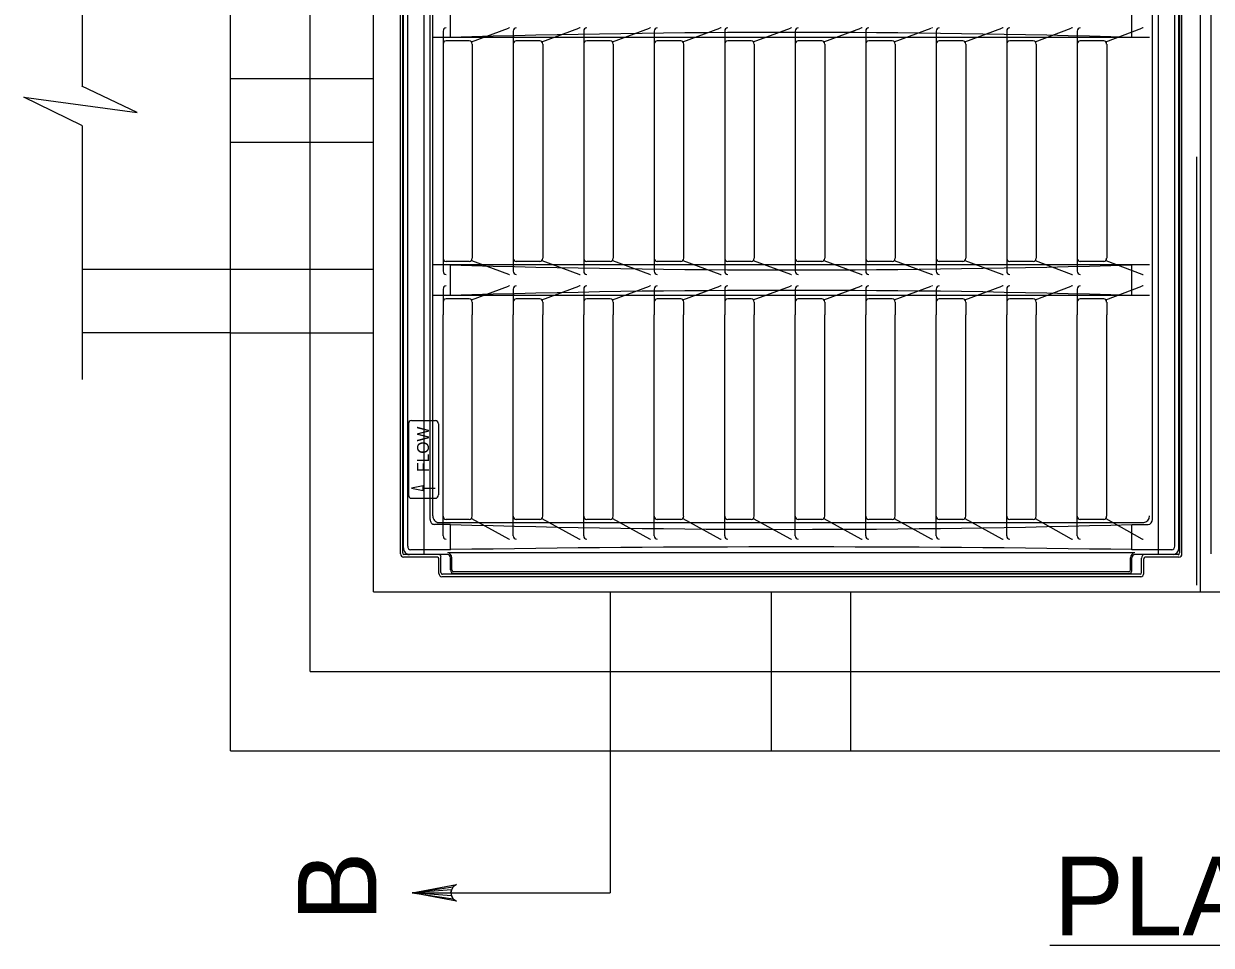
# Model space of a CAD drawing. Extents: x 6.91 to 13.84, y 0.35 to 9.99.
# Drawn here: x 7.133 to 8.644, y 7.952 to 9.125 of the extents above; entities that cross this region are included whole.
import ezdxf

# ---------------------------------------------------------------- set-up
doc = ezdxf.new("R2010")
doc.units = 0
for name, color, linetype in [('DETL-DIMS', 7, 'Continuous'), ('DETL-LINE', 7, 'Continuous'), ('DETL-NOTE', 7, 'Continuous'), ('DETL-TITL', 7, 'Continuous')]:
    doc.layers.add(name, color=color, linetype=linetype)

msp = doc.modelspace()

# ---------------------------------------------------------------- linework, layer by layer
at = {"layer": 'DETL-DIMS'}
for p in [(7.8795, 8.4019), (7.6276, 8.0189)]:
    msp.add_line(p, (7.8795, 8.0189), dxfattribs=at)
msp.add_lwpolyline([(7.6276, 8.0189), (7.6841, 8.0295), (7.6798, 8.0265), (7.6775, 8.0227), (7.6769, 8.0189), (7.6775, 8.0151), (7.6798, 8.0113), (7.6841, 8.0083), (7.6276, 8.0189), (7.6798, 8.0113), (7.6775, 8.0151), (7.6276, 8.0189), (7.6769, 8.0189), (7.6775, 8.0227), (7.6276, 8.0189), (7.6798, 8.0265)], dxfattribs=at)
at = {"layer": 'DETL-LINE'}
for p, q in [((7.3965, 8.1996), (7.3965, 9.7427)), ((7.4976, 8.3007), (7.4976, 9.6214)), ((7.5785, 8.4019), (7.5785, 9.5203)), ((8.6303, 9.5203), (8.6303, 8.4019)), ((7.6128, 8.4504), (7.6128, 9.4776)), ((7.6156, 8.4514), (7.6156, 9.4765)), ((7.6427, 8.4495), (7.6427, 9.476)), ((8.577, 8.4495), (8.577, 9.476)), ((8.6041, 8.4514), (8.6041, 9.4765)), ((8.6069, 8.4504), (8.6069, 9.4776)), ((8.6443, 8.4504), (8.6443, 9.4776)), ((7.6219, 8.4599), (7.6219, 9.4656)), ((8.5979, 8.4599), (8.5979, 9.4656)), ((8.5694, 8.4942), (8.5694, 9.4313)), ((7.6503, 8.4942), (7.6503, 9.4278)), ((7.6539, 8.4988), (7.6539, 9.4267)), ((7.2076, 9.3519), (7.2076, 9.0456)), ((7.6764, 9.1074), (7.6764, 9.1463)), ((8.5434, 9.1074), (8.5434, 9.1463)), ((8.5658, 9.1074), (7.6539, 9.1074)), ((7.3965, 9.0551), (7.5785, 9.0551)), ((7.2076, 8.9955), (7.2076, 8.6723)), ((7.3965, 8.9742), (7.5785, 8.9742)), ((8.626, 8.4104), (8.626, 8.9554)), ((7.2076, 8.8124), (7.5785, 8.8124)), ((8.5658, 8.8181), (7.6539, 8.8181)), ((7.6764, 8.7791), (7.6764, 8.8181)), ((8.5434, 8.7791), (8.5434, 8.8181)), ((8.5658, 8.7791), (7.6539, 8.7791)), ((7.3965, 8.7315), (7.2076, 8.7315)), ((7.3965, 8.7315), (7.5785, 8.7315)), ((7.6764, 8.4877), (7.6559, 8.4877)), ((7.6614, 8.4902), (8.5583, 8.4902)), ((7.6764, 8.4556), (7.6764, 8.4877)), ((8.5434, 8.4877), (8.5638, 8.4877)), ((8.5434, 8.4556), (8.5434, 8.4877)), ((7.6596, 8.4461), (7.6166, 8.4461)), ((7.6624, 8.4493), (7.6175, 8.4493)), ((7.6764, 8.4556), (7.6256, 8.4556)), ((7.6427, 8.4493), (7.6427, 8.4495)), ((7.6642, 8.4266), (7.6642, 8.4471)), ((8.5471, 8.4516), (7.6733, 8.4516)), ((8.5941, 8.4556), (8.5434, 8.4556)), ((8.6022, 8.4493), (8.5593, 8.4493)), ((8.6032, 8.4461), (8.5602, 8.4461)), ((8.577, 8.4493), (8.577, 8.4495)), ((7.6614, 8.4255), (7.6614, 8.4439)), ((7.6781, 8.4298), (7.6781, 8.4452)), ((8.5416, 8.4298), (8.5416, 8.4452)), ((8.5555, 8.4266), (8.5555, 8.445)), ((8.5583, 8.4255), (8.5583, 8.4439)), ((8.5546, 8.4212), (7.6652, 8.4212)), ((8.5537, 8.4245), (7.6661, 8.4245)), ((8.5396, 8.4276), (7.6801, 8.4276)), ((7.5785, 8.4019), (9.682, 8.4019)), ((8.0842, 8.4019), (8.0842, 8.1996)), ((8.1853, 8.4019), (8.1853, 8.1996)), ((7.4976, 8.3007), (9.7629, 8.3007)), ((7.3965, 8.1996), (9.864, 8.1996))]:
    msp.add_line(p, q, dxfattribs=at)
msp.add_lwpolyline([(7.2071, 8.9955), (7.1334, 9.0316), (7.2777, 9.012), (7.2071, 9.0456)], dxfattribs=at)
for centre, major_axis, start_param, end_param in [((8.1099, -10.1659), (0, 19.2797), 6.257325, 6.309046), ((8.1099, 28.0913), (0, 19.2797), 3.115732, 3.167453), ((8.1099, -10.4941), (0, 19.2797), 6.257325, 6.309046), ((7.6559, 8.4942), (0, 0.00645), 1.570796, 3.141593), ((7.6614, 8.4988), (0, 0.0086), 1.570796, 3.141593), ((8.5583, 8.4988), (0, 0.0086), 3.141593, 4.712389), ((8.5638, 8.4942), (0, 0.00645), 3.141593, 4.712389), ((8.1099, 28.6478), (0, 20.1663), 3.116869, 3.166316), ((7.6166, 8.4504), (0, 0.0043), 1.570796, 3.141593), ((7.6175, 8.4514), (0, 0.00215), 1.570796, 3.141593), ((7.6256, 8.4599), (0, 0.0043), 1.570796, 3.141593), ((7.6596, 8.4439), (0, 0.00215), 4.712389, 6.283185), ((7.6624, 8.4471), (0, 0.00215), 4.712389, 6.283185), ((7.6726, 8.4452), (0, 0.00632), 4.712389, 6.283185), ((8.1099, -27.686), (0, 36.1451), 6.269392, 6.296978), ((8.5471, 8.4452), (0, 0.00632), 0, 1.570796), ((8.5593, 8.445), (0, 0.0043), 0, 1.570796), ((8.5602, 8.4439), (0, 0.00215), 0, 1.570796), ((8.5941, 8.4599), (0, 0.0043), 3.141593, 4.712389), ((8.6022, 8.4514), (0, 0.00215), 3.141593, 4.712389), ((8.6032, 8.4504), (0, 0.0043), 3.141593, 4.712389), ((7.6652, 8.4255), (0, 0.0043), 1.570796, 3.141593), ((7.6661, 8.4266), (0, 0.00215), 1.570796, 3.141593), ((7.6801, 8.4298), (0, 0.00227), 1.570796, 3.141593), ((8.5396, 8.4298), (0, 0.00227), 3.141593, 4.712389), ((8.5537, 8.4266), (0, 0.00215), 3.141593, 4.712389), ((8.5546, 8.4255), (0, 0.0043), 3.141593, 4.712389)]:
    msp.add_ellipse(centre, major_axis=major_axis, ratio=0.869565, start_param=start_param, end_param=end_param, dxfattribs=at)
at = {"layer": 'DETL-NOTE'}
for p, q in [((7.6166, 8.4581), (7.6166, 9.4674)), ((8.6032, 8.4581), (8.6032, 9.4674)), ((7.667, 9.1153), (7.667, 8.8101)), ((7.7029, 9.1018), (7.75, 9.1192)), ((7.7562, 9.1153), (7.7562, 8.8101)), ((7.7926, 9.1018), (7.8397, 9.1192)), ((7.8459, 9.1153), (7.8459, 8.8101)), ((7.8823, 9.1018), (7.9294, 9.1192)), ((7.9356, 9.1153), (7.9356, 8.8101)), ((7.9719, 9.1018), (8.0191, 9.1192)), ((8.0253, 9.1153), (8.0253, 8.8101)), ((8.0616, 9.1018), (8.1088, 9.1192)), ((8.115, 9.1153), (8.115, 8.8101)), ((8.1513, 9.1018), (8.1985, 9.1192)), ((8.2047, 9.1153), (8.2047, 8.8101)), ((8.241, 9.1018), (8.2881, 9.1192)), ((8.2944, 9.1153), (8.2944, 8.8101)), ((8.3307, 9.1018), (8.3778, 9.1192)), ((8.3841, 9.1153), (8.3841, 8.8101)), ((8.4204, 9.1018), (8.4661, 9.1192)), ((8.4737, 9.1153), (8.4737, 8.8101)), ((8.5101, 9.1018), (8.5558, 9.1192)), ((7.7002, 9.1031), (7.6707, 9.1031)), ((7.704, 9.0988), (7.704, 8.8267)), ((7.7899, 9.1031), (7.76, 9.1031)), ((7.7937, 9.0988), (7.7937, 8.8267)), ((7.8796, 9.1031), (7.8496, 9.1031)), ((7.8834, 9.0988), (7.8834, 8.8267)), ((7.9693, 9.1031), (7.9393, 9.1031)), ((7.973, 9.0988), (7.973, 8.8267)), ((8.059, 9.1031), (8.029, 9.1031)), ((8.0627, 9.0988), (8.0627, 8.8267)), ((8.1487, 9.1031), (8.1187, 9.1031)), ((8.1524, 9.0988), (8.1524, 8.8267)), ((8.2384, 9.1031), (8.2084, 9.1031)), ((8.2421, 9.0988), (8.2421, 8.8267)), ((8.3281, 9.1031), (8.2981, 9.1031)), ((8.3318, 9.0988), (8.3318, 8.8267)), ((8.4178, 9.1031), (8.3878, 9.1031)), ((8.4215, 9.0988), (8.4215, 8.8267)), ((8.5074, 9.1031), (8.4775, 9.1031)), ((8.5112, 9.0988), (8.5112, 8.8267)), ((7.7029, 8.8237), (7.75, 8.8063)), ((7.7926, 8.8237), (7.8397, 8.8063)), ((7.8823, 8.8237), (7.9294, 8.8063)), ((7.9719, 8.8237), (8.0191, 8.8063)), ((8.0616, 8.8237), (8.1088, 8.8063)), ((8.1513, 8.8237), (8.1985, 8.8063)), ((8.241, 8.8237), (8.2881, 8.8063)), ((8.3307, 8.8237), (8.3778, 8.8063)), ((8.4204, 8.8237), (8.4661, 8.8063)), ((8.5101, 8.8237), (8.5558, 8.8063)), ((7.7002, 8.8224), (7.6707, 8.8224)), ((7.7899, 8.8224), (7.76, 8.8224)), ((7.8796, 8.8224), (7.8496, 8.8224)), ((7.9693, 8.8224), (7.9393, 8.8224)), ((8.059, 8.8224), (8.029, 8.8224)), ((8.1487, 8.8224), (8.1187, 8.8224)), ((8.2384, 8.8224), (8.2084, 8.8224)), ((8.3281, 8.8224), (8.2981, 8.8224)), ((8.4178, 8.8224), (8.3878, 8.8224)), ((8.5074, 8.8224), (8.4775, 8.8224)), ((7.667, 8.7871), (7.667, 8.7546)), ((7.7029, 8.7736), (7.75, 8.791)), ((7.7562, 8.7871), (7.7562, 8.7546)), ((7.7926, 8.7736), (7.8397, 8.791)), ((7.8459, 8.7871), (7.8459, 8.7546)), ((7.8823, 8.7736), (7.9294, 8.791)), ((7.9356, 8.7871), (7.9356, 8.7546)), ((7.9719, 8.7736), (8.0191, 8.791)), ((8.0253, 8.7871), (8.0253, 8.7546)), ((8.0616, 8.7736), (8.1088, 8.791)), ((8.115, 8.7871), (8.115, 8.7546)), ((8.1513, 8.7736), (8.1985, 8.791)), ((8.2047, 8.7871), (8.2047, 8.7546)), ((8.241, 8.7736), (8.2881, 8.791)), ((8.2944, 8.7871), (8.2944, 8.7546)), ((8.3307, 8.7736), (8.3778, 8.791)), ((8.3841, 8.7871), (8.3841, 8.7546)), ((8.4204, 8.7736), (8.4661, 8.791)), ((8.4737, 8.7871), (8.4737, 8.7546)), ((8.5101, 8.7736), (8.5558, 8.791)), ((7.7002, 8.7748), (7.6707, 8.7748)), ((7.704, 8.7705), (7.704, 8.7546)), ((7.7899, 8.7748), (7.76, 8.7748)), ((7.7937, 8.7705), (7.7937, 8.7546)), ((7.8796, 8.7748), (7.8496, 8.7748)), ((7.8834, 8.7705), (7.8834, 8.7546)), ((7.9693, 8.7748), (7.9393, 8.7748)), ((7.973, 8.7705), (7.973, 8.7546)), ((8.059, 8.7748), (8.029, 8.7748)), ((8.0627, 8.7705), (8.0627, 8.7546)), ((8.1487, 8.7748), (8.1187, 8.7748)), ((8.1524, 8.7705), (8.1524, 8.7546)), ((8.2384, 8.7748), (8.2084, 8.7748)), ((8.2421, 8.7705), (8.2421, 8.7546)), ((8.3281, 8.7748), (8.2981, 8.7748)), ((8.3318, 8.7705), (8.3318, 8.7546)), ((8.4178, 8.7748), (8.3878, 8.7748)), ((8.4215, 8.7705), (8.4215, 8.7546)), ((8.5074, 8.7748), (8.4775, 8.7748)), ((8.5112, 8.7705), (8.5112, 8.7546)), ((7.667, 8.4732), (7.667, 8.7546)), ((7.704, 8.4983), (7.704, 8.7546)), ((7.7562, 8.4732), (7.7562, 8.7546)), ((7.7937, 8.4983), (7.7937, 8.7546)), ((7.8459, 8.4732), (7.8459, 8.7546)), ((7.8834, 8.4983), (7.8834, 8.7546)), ((7.9356, 8.4732), (7.9356, 8.7546)), ((7.973, 8.4983), (7.973, 8.7546)), ((8.0253, 8.4732), (8.0253, 8.7546)), ((8.0627, 8.4983), (8.0627, 8.7546)), ((8.115, 8.4732), (8.115, 8.7546)), ((8.1524, 8.4983), (8.1524, 8.7546)), ((8.2047, 8.4732), (8.2047, 8.7546)), ((8.2421, 8.4983), (8.2421, 8.7546)), ((8.2944, 8.4732), (8.2944, 8.7546)), ((8.3318, 8.4983), (8.3318, 8.7546)), ((8.3841, 8.4732), (8.3841, 8.7546)), ((8.4215, 8.4983), (8.4215, 8.7546)), ((8.4737, 8.4732), (8.4737, 8.7546)), ((8.5112, 8.4983), (8.5112, 8.7546)), ((7.6229, 8.6156), (7.6229, 8.5253)), ((7.6266, 8.6199), (7.6572, 8.6199)), ((7.661, 8.6156), (7.661, 8.5253)), ((7.6416, 8.5339), (7.657, 8.5339)), ((7.6266, 8.521), (7.6572, 8.521)), ((7.7002, 8.4941), (7.6707, 8.4941)), ((7.7029, 8.4953), (7.75, 8.4693)), ((7.7899, 8.4941), (7.76, 8.4941)), ((7.7926, 8.4953), (7.8397, 8.4693)), ((7.8796, 8.4941), (7.8496, 8.4941)), ((7.8823, 8.4953), (7.9294, 8.4693)), ((7.9693, 8.4941), (7.9393, 8.4941)), ((7.9719, 8.4953), (8.0191, 8.4693)), ((8.059, 8.4941), (8.029, 8.4941)), ((8.0616, 8.4953), (8.1088, 8.4693)), ((8.1487, 8.4941), (8.1187, 8.4941)), ((8.1513, 8.4953), (8.1985, 8.4693)), ((8.2384, 8.4941), (8.2084, 8.4941)), ((8.241, 8.4953), (8.2881, 8.4693)), ((8.3281, 8.4941), (8.2981, 8.4941)), ((8.3307, 8.4953), (8.3778, 8.4693)), ((8.4178, 8.4941), (8.3878, 8.4941)), ((8.4204, 8.4953), (8.4661, 8.4693)), ((8.5074, 8.4941), (8.4775, 8.4941)), ((8.5101, 8.4953), (8.5558, 8.4693)), ((7.6726, 8.4495), (7.624, 8.4495)), ((8.5957, 8.4495), (8.5471, 8.4495)), ((7.6764, 8.4298), (7.6764, 8.4452)), ((7.6764, 8.4409), (7.6764, 8.4451)), ((8.5434, 8.4298), (8.5434, 8.4452)), ((7.6801, 8.4255), (8.5396, 8.4255))]:
    msp.add_line(p, q, dxfattribs=at)
msp.add_lwpolyline([(7.6416, 8.531), (7.6416, 8.5367), (7.6266, 8.5339)], close=True, dxfattribs=at)
for centre, major_axis, start_param, end_param in [((7.6707, 9.1153), (0, 0.0043), 0, 1.570796), ((7.7516, 9.1153), (0, 0.0043), 0, 0.447297), ((7.76, 9.1153), (0, 0.0043), 0, 1.570796), ((7.8413, 9.1153), (0, 0.0043), 0, 0.447297), ((7.8496, 9.1153), (0, 0.0043), 0, 1.570796), ((7.931, 9.1153), (0, 0.0043), 0, 0.447297), ((7.9393, 9.1153), (0, 0.0043), 0, 1.570796), ((8.0207, 9.1153), (0, 0.0043), 0, 0.447297), ((8.029, 9.1153), (0, 0.0043), 0, 1.570796), ((8.1104, 9.1153), (0, 0.0043), 0, 0.447297), ((8.1187, 9.1153), (0, 0.0043), 0, 1.570796), ((8.2001, 9.1153), (0, 0.0043), 0, 0.447297), ((8.2084, 9.1153), (0, 0.0043), 0, 1.570796), ((8.2898, 9.1153), (0, 0.0043), 0, 0.447297), ((8.2981, 9.1153), (0, 0.0043), 0, 1.570796), ((8.3795, 9.1153), (0, 0.0043), 0, 0.447297), ((8.3878, 9.1153), (0, 0.0043), 0, 1.570796), ((8.4678, 9.1153), (0, 0.0043), 0, 0.447297), ((8.4775, 9.1153), (0, 0.0043), 0, 1.570796), ((8.5575, 9.1153), (0, 0.0043), 0, 0.447297), ((7.6707, 9.0988), (0, 0.0043), 0, 1.570796), ((7.7002, 9.0988), (0, 0.0043), 4.712389, 6.283185), ((7.76, 9.0988), (0, 0.0043), 0, 1.570796), ((7.7899, 9.0988), (0, 0.0043), 4.712389, 6.283185), ((7.8496, 9.0988), (0, 0.0043), 0, 1.570796), ((7.8796, 9.0988), (0, 0.0043), 4.712389, 6.283185), ((7.9393, 9.0988), (0, 0.0043), 0, 1.570796), ((7.9693, 9.0988), (0, 0.0043), 4.712389, 6.283185), ((8.029, 9.0988), (0, 0.0043), 0, 1.570796), ((8.059, 9.0988), (0, 0.0043), 4.712389, 6.283185), ((8.1187, 9.0988), (0, 0.0043), 0, 1.570796), ((8.1487, 9.0988), (0, 0.0043), 4.712389, 6.283185), ((8.2084, 9.0988), (0, 0.0043), 0, 1.570796), ((8.2384, 9.0988), (0, 0.0043), 4.712389, 6.283185), ((8.2981, 9.0988), (0, 0.0043), 0, 1.570796), ((8.3281, 9.0988), (0, 0.0043), 4.712389, 6.283185), ((8.3878, 9.0988), (0, 0.0043), 0, 1.570796), ((8.4178, 9.0988), (0, 0.0043), 4.712389, 6.283185), ((8.4775, 9.0988), (0, 0.0043), 0, 1.570796), ((8.5074, 9.0988), (0, 0.0043), 4.712389, 6.283185), ((7.6707, 8.8267), (0, 0.0043), 1.570796, 3.141593), ((7.7002, 8.8267), (0, 0.0043), 3.141593, 4.712389), ((7.76, 8.8267), (0, 0.0043), 1.570796, 3.141593), ((7.7899, 8.8267), (0, 0.0043), 3.141593, 4.712389), ((7.8496, 8.8267), (0, 0.0043), 1.570796, 3.141593), ((7.8796, 8.8267), (0, 0.0043), 3.141593, 4.712389), ((7.9393, 8.8267), (0, 0.0043), 1.570796, 3.141593), ((7.9693, 8.8267), (0, 0.0043), 3.141593, 4.712389), ((8.029, 8.8267), (0, 0.0043), 1.570796, 3.141593), ((8.059, 8.8267), (0, 0.0043), 3.141593, 4.712389), ((8.1187, 8.8267), (0, 0.0043), 1.570796, 3.141593), ((8.1487, 8.8267), (0, 0.0043), 3.141593, 4.712389), ((8.2084, 8.8267), (0, 0.0043), 1.570796, 3.141593), ((8.2384, 8.8267), (0, 0.0043), 3.141593, 4.712389), ((8.2981, 8.8267), (0, 0.0043), 1.570796, 3.141593), ((8.3281, 8.8267), (0, 0.0043), 3.141593, 4.712389), ((8.3878, 8.8267), (0, 0.0043), 1.570796, 3.141593), ((8.4178, 8.8267), (0, 0.0043), 3.141593, 4.712389), ((8.4775, 8.8267), (0, 0.0043), 1.570796, 3.141593), ((8.5074, 8.8267), (0, 0.0043), 3.141593, 4.712389), ((7.6707, 8.8101), (0, 0.0043), 1.570796, 3.141593), ((7.76, 8.8101), (0, 0.0043), 1.570796, 3.141593), ((7.8496, 8.8101), (0, 0.0043), 1.570796, 3.141593), ((7.9393, 8.8101), (0, 0.0043), 1.570796, 3.141593), ((8.029, 8.8101), (0, 0.0043), 1.570796, 3.141593), ((8.1187, 8.8101), (0, 0.0043), 1.570796, 3.141593), ((8.2084, 8.8101), (0, 0.0043), 1.570796, 3.141593), ((8.2981, 8.8101), (0, 0.0043), 1.570796, 3.141593), ((8.3878, 8.8101), (0, 0.0043), 1.570796, 3.141593), ((8.4775, 8.8101), (0, 0.0043), 1.570796, 3.141593), ((7.7516, 8.8101), (0, 0.0043), 2.694296, 3.141593), ((7.8413, 8.8101), (0, 0.0043), 2.694296, 3.141593), ((7.931, 8.8101), (0, 0.0043), 2.694296, 3.141593), ((8.0207, 8.8101), (0, 0.0043), 2.694296, 3.141593), ((8.1104, 8.8101), (0, 0.0043), 2.694296, 3.141593), ((8.2001, 8.8101), (0, 0.0043), 2.694296, 3.141593), ((8.2898, 8.8101), (0, 0.0043), 2.694296, 3.141593), ((8.3795, 8.8101), (0, 0.0043), 2.694296, 3.141593), ((8.4678, 8.8101), (0, 0.0043), 2.694296, 3.141593), ((8.5575, 8.8101), (0, 0.0043), 2.694296, 3.141593), ((7.6707, 8.7871), (0, 0.0043), 0, 1.570796), ((7.7516, 8.7871), (0, 0.0043), 0, 0.447297), ((7.76, 8.7871), (0, 0.0043), 0, 1.570796), ((7.8413, 8.7871), (0, 0.0043), 0, 0.447297), ((7.8496, 8.7871), (0, 0.0043), 0, 1.570796), ((7.931, 8.7871), (0, 0.0043), 0, 0.447297), ((7.9393, 8.7871), (0, 0.0043), 0, 1.570796), ((8.0207, 8.7871), (0, 0.0043), 0, 0.447297), ((8.029, 8.7871), (0, 0.0043), 0, 1.570796), ((8.1104, 8.7871), (0, 0.0043), 0, 0.447297), ((8.1187, 8.7871), (0, 0.0043), 0, 1.570796), ((8.2001, 8.7871), (0, 0.0043), 0, 0.447297), ((8.2084, 8.7871), (0, 0.0043), 0, 1.570796), ((8.2898, 8.7871), (0, 0.0043), 0, 0.447297), ((8.2981, 8.7871), (0, 0.0043), 0, 1.570796), ((8.3795, 8.7871), (0, 0.0043), 0, 0.447297), ((8.3878, 8.7871), (0, 0.0043), 0, 1.570796), ((8.4678, 8.7871), (0, 0.0043), 0, 0.447297), ((8.4775, 8.7871), (0, 0.0043), 0, 1.570796), ((8.5575, 8.7871), (0, 0.0043), 0, 0.447297), ((7.6707, 8.7705), (0, 0.0043), 0, 1.570796), ((7.7002, 8.7705), (0, 0.0043), 4.712389, 6.283185), ((7.76, 8.7705), (0, 0.0043), 0, 1.570796), ((7.7899, 8.7705), (0, 0.0043), 4.712389, 6.283185), ((7.8496, 8.7705), (0, 0.0043), 0, 1.570796), ((7.8796, 8.7705), (0, 0.0043), 4.712389, 6.283185), ((7.9393, 8.7705), (0, 0.0043), 0, 1.570796), ((7.9693, 8.7705), (0, 0.0043), 4.712389, 6.283185), ((8.029, 8.7705), (0, 0.0043), 0, 1.570796), ((8.059, 8.7705), (0, 0.0043), 4.712389, 6.283185), ((8.1187, 8.7705), (0, 0.0043), 0, 1.570796), ((8.1487, 8.7705), (0, 0.0043), 4.712389, 6.283185), ((8.2084, 8.7705), (0, 0.0043), 0, 1.570796), ((8.2384, 8.7705), (0, 0.0043), 4.712389, 6.283185), ((8.2981, 8.7705), (0, 0.0043), 0, 1.570796), ((8.3281, 8.7705), (0, 0.0043), 4.712389, 6.283185), ((8.3878, 8.7705), (0, 0.0043), 0, 1.570796), ((8.4178, 8.7705), (0, 0.0043), 4.712389, 6.283185), ((8.4775, 8.7705), (0, 0.0043), 0, 1.570796), ((8.5074, 8.7705), (0, 0.0043), 4.712389, 6.283185), ((7.6266, 8.6156), (0, 0.0043), 0, 1.570796), ((7.6572, 8.6156), (0, 0.0043), 4.712389, 6.283185), ((7.6266, 8.5253), (0, 0.0043), 1.570796, 3.141593), ((7.6572, 8.5253), (0, 0.0043), 3.141593, 4.712389), ((7.6707, 8.4983), (0, 0.0043), 1.570796, 3.141593), ((7.7002, 8.4983), (0, 0.0043), 3.141593, 4.712389), ((7.76, 8.4983), (0, 0.0043), 1.570796, 3.141593), ((7.7899, 8.4983), (0, 0.0043), 3.141593, 4.712389), ((7.8496, 8.4983), (0, 0.0043), 1.570796, 3.141593), ((7.8796, 8.4983), (0, 0.0043), 3.141593, 4.712389), ((7.9393, 8.4983), (0, 0.0043), 1.570796, 3.141593), ((7.9693, 8.4983), (0, 0.0043), 3.141593, 4.712389), ((8.029, 8.4983), (0, 0.0043), 1.570796, 3.141593), ((8.059, 8.4983), (0, 0.0043), 3.141593, 4.712389), ((8.1187, 8.4983), (0, 0.0043), 1.570796, 3.141593), ((8.1487, 8.4983), (0, 0.0043), 3.141593, 4.712389), ((8.2084, 8.4983), (0, 0.0043), 1.570796, 3.141593), ((8.2384, 8.4983), (0, 0.0043), 3.141593, 4.712389), ((8.2981, 8.4983), (0, 0.0043), 1.570796, 3.141593), ((8.3281, 8.4983), (0, 0.0043), 3.141593, 4.712389), ((8.3878, 8.4983), (0, 0.0043), 1.570796, 3.141593), ((8.4178, 8.4983), (0, 0.0043), 3.141593, 4.712389), ((8.4775, 8.4983), (0, 0.0043), 1.570796, 3.141593), ((8.5074, 8.4983), (0, 0.0043), 3.141593, 4.712389), ((7.6707, 8.4732), (0, 0.0043), 1.570796, 3.141593), ((7.7516, 8.4732), (0, 0.0043), 2.694296, 3.141593), ((7.76, 8.4732), (0, 0.0043), 1.570796, 3.141593), ((7.8413, 8.4732), (0, 0.0043), 2.694296, 3.141593), ((7.8496, 8.4732), (0, 0.0043), 1.570796, 3.141593), ((7.931, 8.4732), (0, 0.0043), 2.694296, 3.141593), ((7.9393, 8.4732), (0, 0.0043), 1.570796, 3.141593), ((8.0207, 8.4732), (0, 0.0043), 2.694296, 3.141593), ((8.029, 8.4732), (0, 0.0043), 1.570796, 3.141593), ((8.1104, 8.4732), (0, 0.0043), 2.694296, 3.141593), ((8.1187, 8.4732), (0, 0.0043), 1.570796, 3.141593), ((8.2001, 8.4732), (0, 0.0043), 2.694296, 3.141593), ((8.2084, 8.4732), (0, 0.0043), 1.570796, 3.141593), ((8.2898, 8.4732), (0, 0.0043), 2.694296, 3.141593), ((8.2981, 8.4732), (0, 0.0043), 1.570796, 3.141593), ((8.3795, 8.4732), (0, 0.0043), 2.694296, 3.141593), ((8.3878, 8.4732), (0, 0.0043), 1.570796, 3.141593), ((8.4678, 8.4732), (0, 0.0043), 2.694296, 3.141593), ((8.4775, 8.4732), (0, 0.0043), 1.570796, 3.141593), ((8.5575, 8.4732), (0, 0.0043), 2.694296, 3.141593), ((7.624, 8.4581), (0, 0.0086), 1.570796, 3.141593), ((7.6726, 8.4452), (0, 0.0043), 4.712389, 6.283185), ((8.5471, 8.4452), (0, 0.0043), 0, 1.570796), ((8.5957, 8.4581), (0, 0.0086), 3.141593, 4.712389), ((7.6801, 8.4298), (0, 0.0043), 1.570796, 3.141593), ((8.5396, 8.4298), (0, 0.0043), 3.141593, 4.712389)]:
    msp.add_ellipse(centre, major_axis=major_axis, ratio=0.869565, start_param=start_param, end_param=end_param, dxfattribs=at)
at = {"layer": 'DETL-TITL'}
msp.add_line((8.4388, 7.9523), (8.8087, 7.9523), dxfattribs=at)

# ---------------------------------------------------------------- texts
at = {"layer": 'DETL-NOTE'}
msp.add_text('FLOW', height=0.01495, rotation=90, dxfattribs=at).set_placement((7.6488, 8.5544))
at = {"layer": 'DETL-TITL'}
msp.add_text('B', height=0.1, rotation=90, dxfattribs=at).set_placement((7.5821, 7.9822))
msp.add_text('PLAN', height=0.10012, dxfattribs=at).set_placement((8.4439, 7.9649))

doc.saveas('drawing.dxf')
